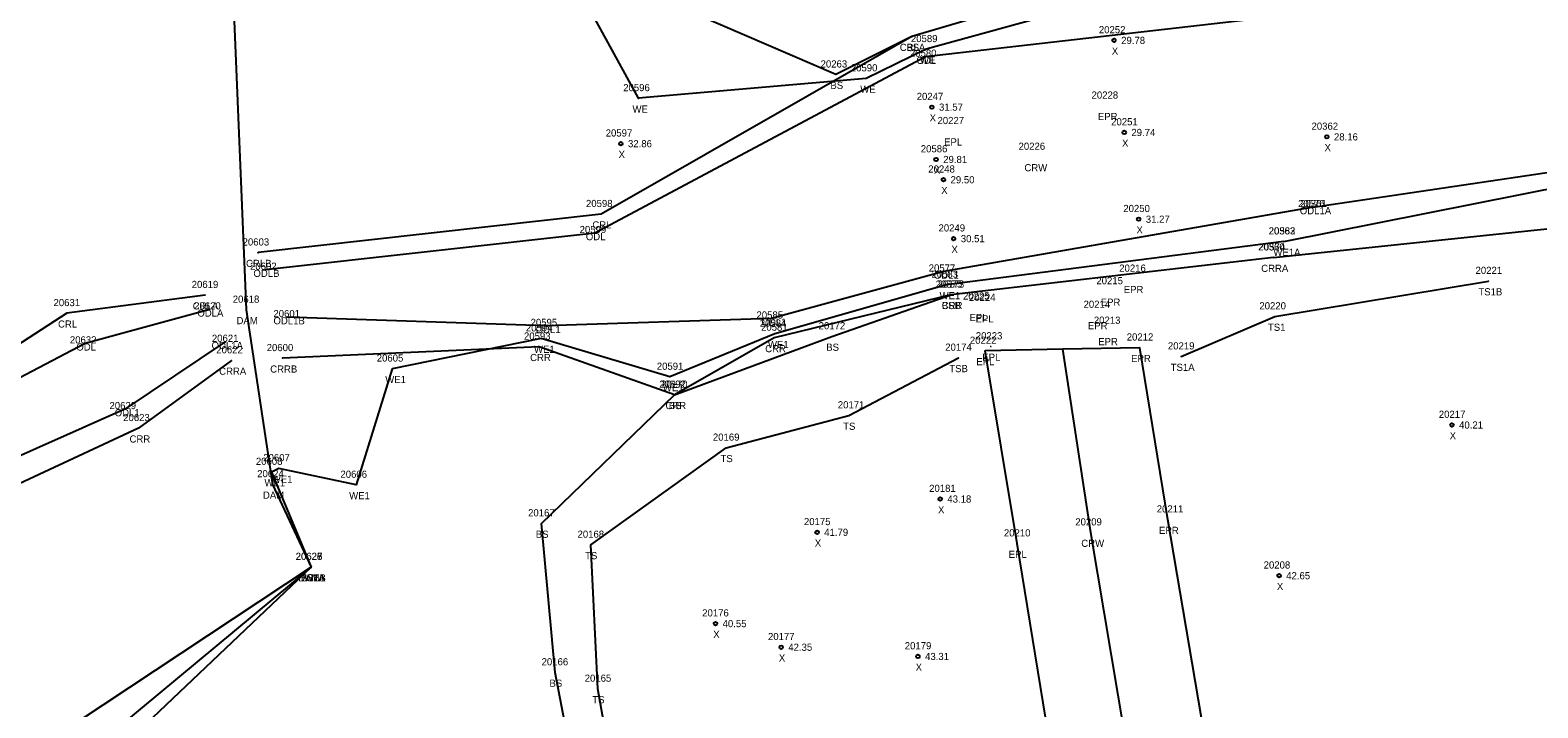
# Model space of a CAD drawing. Extents: x 2445178 to 2446260, y 791158 to 792318.
# Drawn here: x 2445572.9 to 2445783.8, y 791715.3 to 791810 of the extents above; entities that cross this region are included whole.
import ezdxf

# ---------------------------------------------------------------- set-up
doc = ezdxf.new("R2010")
doc.units = 0
for name, color, linetype in [('RD_DTM_BkLn1', 7, 'Continuous'), ('RD_DTM_BkLn2', 7, 'Continuous'), ('RD_EX_Dam', 7, 'Continuous'), ('RD_EX_Dam_txCode', 7, 'Continuous'), ('RD_EX_H2O', 7, 'Continuous'), ('RD_EX_H2O_txCode', 7, 'Continuous'), ('RD_EX_Road', 7, 'Continuous'), ('RD_EX_Road_txCode', 7, 'Continuous'), ('RD_Sketch8', 7, 'Continuous'), ('RD_SMD_Locator', 7, 'Continuous'), ('RD_SMD_Misc', 7, 'Continuous')]:
    doc.layers.add(name, color=color, linetype=linetype)

msp = doc.modelspace()

# ---------------------------------------------------------------- linework, layer by layer
at = {"layer": 'RD_DTM_BkLn1'}
for points in [[(2445728.16, 791765.65), (2445717.39, 791765.43), (2445706.49, 791765.2)], [(2445860.1, 791179.04), (2445833.11, 791268.21), (2445816.53, 791324.11), (2445799.46, 791383.44), (2445783.89, 791440.59), (2445769.57, 791497.35), (2445755.95, 791556.11), (2445741.36, 791625.36), (2445732.84, 791671.31), (2445721.28, 791739.8), (2445717.39, 791765.43)]]:
    msp.add_lwpolyline(points, dxfattribs=at)
at = {"layer": 'RD_DTM_BkLn2'}
for points in [[(2445721.97, 791816.74), (2445696.27, 791809.15), (2445685.63, 791803.83), (2445656.7, 791816.36), (2445642.32, 791839.59), (2445634.31, 791862.06), (2445625.81, 791909.02), (2445601.16, 791980.42), (2445587.75, 792035.69), (2445589.15, 792093.24), (2445629.12, 792201.55), (2445634.25, 792303.36)], [(2445733.92, 791764.41), (2445747.04, 791770.01), (2445776.96, 791774.97)], [(2445660.9, 791679.61), (2445652.02, 791690.62), (2445646.32, 791720.24), (2445644.41, 791741.07), (2445663.02, 791759.06), (2445685.05, 791767.22), (2445701.7, 791773.05)], [(2445660.9, 791679.61), (2445657.03, 791691.38), (2445652.33, 791717.94), (2445651.33, 791738.08), (2445670.27, 791751.65), (2445687.44, 791756.17), (2445702.76, 791764.23)], [(2445612.18, 791734.98), (2445557.56, 791698.84), (2445552.02, 791673.05), (2445513.68, 791664.7), (2445463.32, 791637.22), (2445363.77, 791592.3), (2445292.26, 791558.82)], [(2445612.18, 791734.98), (2445563.15, 791688.49), (2445558.95, 791665.85), (2445520.9, 791652.98), (2445473.7, 791621.85), (2445363.77, 791592.3)]]:
    msp.add_lwpolyline(points, dxfattribs=at)
at = {"layer": 'RD_EX_Dam'}
msp.add_lwpolyline([(2445642.32, 791839.59), (2445601.3, 791814.78), (2445603.08, 791770.94), (2445606.78, 791746.54), (2445612.18, 791734.98)], dxfattribs=at)
at = {"layer": 'RD_EX_H2O'}
for points in [[(2445748.32, 791780.49), (2445788.24, 791788.44), (2445846, 791811.01), (2445891.85, 791826.96), (2445872.2, 791885.31), (2445911.58, 791917.24), (2445942.41, 791930.41), (2445989.95, 791963.2), (2446004.43, 791957.67), (2446037.13, 791928.19), (2446062.94, 791924.63), (2446122.42, 791925.89), (2446133.98, 791956.62), (2446163.05, 791958.48), (2446202.11, 792005.16)], [(2445752.43, 791785.31), (2445788.27, 791790.61), (2445845.46, 791813.31), (2445889.72, 791828.98), (2445868.44, 791886.37), (2445910.27, 791920.69), (2445939.62, 791931.64), (2445988.31, 791964.33), (2446005.31, 791961.03), (2446034.89, 791932.66), (2446061.86, 791927.42), (2446120.16, 791928.99), (2446131.56, 791958.98), (2446161.23, 791962.03), (2446198.32, 792006.02)], [(2445746.88, 791778.25), (2445790.91, 791782.86), (2445846.87, 791809.11), (2445896.01, 791824.25), (2445877, 791883.78), (2445912.26, 791916.16), (2445942.78, 791927.77), (2445991.6, 791962.06), (2446003.69, 791956.06), (2446036.32, 791927.07), (2446060.96, 791923.67), (2446122.97, 791923.97), (2446134.24, 791956.18), (2446163.21, 791958.01), (2446202.51, 792004.24)], [(2445757.3, 791817.48), (2445724.23, 791814.58), (2445698.23, 791807.38), (2445689.87, 791803.29), (2445658, 791800.52), (2445641.81, 791830.07), (2445642.32, 791839.59), (2445634.31, 791862.06), (2445625.81, 791909.02), (2445601.16, 791980.42)], [(2445756.08, 791812.92), (2445698.14, 791806.34), (2445651.88, 791781.68), (2445605.82, 791776.55)], [(2445696.27, 791809.15), (2445652.77, 791784.32), (2445604.79, 791778.94)], [(2445752.43, 791785.31), (2445700.73, 791776.3), (2445676.63, 791769.73), (2445645.02, 791768.69), (2445608.81, 791769.92)], [(2445748.32, 791780.49), (2445701.12, 791774.43), (2445677.09, 791767.59), (2445662.39, 791761.56), (2445644.36, 791766.93), (2445623.55, 791762.71), (2445618.49, 791746.46), (2445607.67, 791748.78), (2445606.64, 791748.27), (2445612.18, 791734.98), (2445561.56, 791692.97), (2445554.1, 791670.89), (2445517.8, 791656.91), (2445473.7, 791621.85), (2445363.77, 791592.3), (2445292.26, 791558.82)], [(2445746.88, 791778.25), (2445701.7, 791773.05), (2445676.99, 791767.02), (2445663.02, 791759.06), (2445644.08, 791765.78), (2445608.19, 791764.17)], [(2445597.34, 791773), (2445578, 791770.46), (2445544.99, 791749.08)], [(2445598, 791771), (2445580.58, 791766.25), (2445545.35, 791747.76), (2445529.9, 791743.48), (2445493.64, 791702.86), (2445469.99, 791696.32), (2445420.2, 791747.49), (2445408.65, 791738.85), (2445398.22, 791720.47), (2445370.93, 791678.47), (2445333.32, 791699.47), (2445304.17, 791689.05), (2445297.68, 791600.13), (2445290.12, 791566.49)], [(2445600.16, 791766.47), (2445586.11, 791757.06), (2445543.42, 791738.09), (2445500.69, 791690.42), (2445463.87, 791687.89), (2445423.05, 791739.22), (2445412.07, 791732.11), (2445402.24, 791718.7), (2445377.05, 791678.37), (2445370.6, 791674.92), (2445335.15, 791693.03), (2445306.01, 791687.27), (2445304.48, 791597.26), (2445303.65, 791580.6), (2445291.47, 791560.13)], [(2445601.06, 791763.87), (2445588.04, 791754.39), (2445544.11, 791733.92), (2445501.1, 791687.67), (2445464.95, 791685.09), (2445422.11, 791733.61), (2445413.32, 791729.6), (2445404.23, 791718.68), (2445377.21, 791675.18), (2445369.95, 791673.71), (2445335.95, 791691.26), (2445308.99, 791685.23), (2445308.22, 791596.59), (2445306.48, 791581.14), (2445293.31, 791557.11)]]:
    msp.add_lwpolyline(points, dxfattribs=at)
at = {"layer": 'RD_EX_Road'}
for points in [[(2445850.42, 791174.36), (2445823.13, 791264.7), (2445806.34, 791321.46), (2445789.41, 791379.89), (2445773.46, 791437.57), (2445759.36, 791494.22), (2445744.01, 791559.83), (2445740.09, 791577.64), (2445731.05, 791621.01), (2445722.21, 791669.43), (2445711, 791738.26), (2445706.49, 791765.2)], [(2445870.82, 791182.02), (2445844.02, 791271.27), (2445827.31, 791326.39), (2445810.32, 791385.52), (2445794.94, 791441.92), (2445780.98, 791497.5), (2445766.72, 791558.1), (2445751.9, 791628.3), (2445743.63, 791673.52), (2445732.07, 791741.61), (2445728.16, 791765.65)]]:
    msp.add_lwpolyline(points, dxfattribs=at)
at = {"layer": 'RD_SMD_Locator'}
for centre, radius in [((2445696.27, 791809.15), 0.001), ((2445696.27, 791809.15), 0.001), ((2445724.54, 791808.62), 0.25), ((2445698.23, 791807.38), 0.001), ((2445698.14, 791806.34), 0.001), ((2445685.63, 791803.83), 0.001), ((2445689.87, 791803.29), 0.001), ((2445658, 791800.52), 0.001), ((2445699.05, 791799.29), 0.25), ((2445725.97, 791795.75), 0.25), ((2445655.53, 791794.18), 0.25), ((2445754.32, 791795.13), 0.25), ((2445699.64, 791791.97), 0.25), ((2445700.67, 791789.14), 0.25), ((2445652.77, 791784.32), 0.001), ((2445727.99, 791783.62), 0.25), ((2445752.43, 791785.31), 0.001), ((2445752.43, 791785.31), 0.001), ((2445651.88, 791781.68), 0.001), ((2445702.1, 791780.9), 0.25), ((2445748.32, 791780.49), 0.001), ((2445748.32, 791780.49), 0.001), ((2445604.79, 791778.94), 0.001), ((2445746.88, 791778.25), 0.001), ((2445746.88, 791778.25), 0.001), ((2445605.82, 791776.55), 0.001), ((2445700.73, 791776.3), 0.001), ((2445776.96, 791774.97), 0.001), ((2445597.34, 791773), 0.001), ((2445701.12, 791774.43), 0.001), ((2445701.7, 791773.05), 0.001), ((2445701.7, 791773.05), 0.001), ((2445598, 791771), 0.001), ((2445603.08, 791770.94), 0.001), ((2445578, 791770.46), 0.001), ((2445608.81, 791769.92), 0.001), ((2445645.02, 791768.69), 0.001), ((2445676.63, 791769.73), 0.001), ((2445747.04, 791770.01), 0.001), ((2445600.16, 791766.47), 0.001), ((2445644.36, 791766.93), 0.001), ((2445676.99, 791767.02), 0.001), ((2445677.09, 791767.59), 0.001), ((2445685.05, 791767.22), 0.001), ((2445580.58, 791766.25), 0.001), ((2445644.08, 791765.78), 0.001), ((2445706.49, 791765.2), 0.001), ((2445707.32, 791765.82), 0.001), ((2445728.16, 791765.65), 0.001), ((2445733.92, 791764.41), 0.001), ((2445601.06, 791763.87), 0.001), ((2445608.19, 791764.17), 0.001), ((2445623.55, 791762.71), 0.001), ((2445702.76, 791764.23), 0.001), ((2445662.39, 791761.56), 0.001), ((2445663.02, 791759.06), 0.001), ((2445663.02, 791759.06), 0.001), ((2445586.11, 791757.06), 0.001), ((2445687.44, 791756.17), 0.001), ((2445588.04, 791754.39), 0.001), ((2445771.83, 791754.84), 0.25), ((2445670.27, 791751.65), 0.001), ((2445606.64, 791748.27), 0.001), ((2445607.67, 791748.78), 0.001), ((2445606.78, 791746.54), 0.001), ((2445618.49, 791746.46), 0.001), ((2445700.22, 791744.49), 0.25), ((2445732.07, 791741.61), 0.001), ((2445644.41, 791741.07), 0.001), ((2445682.99, 791739.84), 0.25), ((2445721.28, 791739.8), 0.001), ((2445651.33, 791738.08), 0.001), ((2445711, 791738.26), 0.001), ((2445612.18, 791734.98), 0.001), ((2445612.18, 791734.98), 0.001), ((2445612.18, 791734.98), 0.001), ((2445612.18, 791734.98), 0.001), ((2445747.64, 791733.77), 0.25), ((2445668.77, 791727.07), 0.25), ((2445677.96, 791723.77), 0.25), ((2445697.1, 791722.48), 0.25), ((2445646.32, 791720.24), 0.001), ((2445652.33, 791717.94), 0.001)]:
    msp.add_circle(centre, radius, dxfattribs=at)

# ---------------------------------------------------------------- texts
at = {"layer": 'RD_EX_Dam_txCode'}
for s, p in [('20618', (2445601.22, 791771.94)), ('DAM', (2445601.75, 791768.94)), ('20624', (2445604.64, 791747.54)), ('DAM', (2445605.45, 791744.54)), ('20625', (2445610.04, 791735.98)), ('DAMB', (2445610.38, 791732.98))]:
    msp.add_text(s, height=1, dxfattribs=at).set_placement(p)
at = {"layer": 'RD_EX_H2O_txCode'}
for s, p in [('20589', (2445696.12, 791808.38)), ('CRLA', (2445694.56, 791807.15)), ('20580', (2445695.98, 791806.34)), ('20590', (2445687.71, 791804.29)), ('ODL', (2445696.9, 791805.34)), ('WE', (2445697.39, 791805.38)), ('20596', (2445655.86, 791801.52)), ('WE', (2445689.03, 791801.29)), ('WE', (2445657.16, 791798.52)), ('20598', (2445650.65, 791785.32)), ('20576', (2445750.29, 791785.31)), ('20361', (2445750.58, 791785.31)), ('CRL', (2445651.54, 791782.32)), ('ODL1A', (2445750.54, 791784.31)), ('ODL1A', (2445750.54, 791784.31)), ('20599', (2445649.76, 791781.68)), ('ODL', (2445650.63, 791780.68)), ('20363', (2445746.17, 791781.49)), ('20582', (2445746.2, 791781.49)), ('20603', (2445602.6, 791779.94)), ('20360', (2445744.7, 791779.25)), ('20574', (2445744.76, 791779.25)), ('WE1A', (2445746.84, 791778.49)), ('WE1A', (2445746.84, 791778.49)), ('CRLB', (2445603.08, 791776.94)), ('20602', (2445603.64, 791776.55)), ('20577', (2445698.61, 791776.3)), ('CRRA', (2445745.14, 791776.25)), ('CRRA', (2445745.14, 791776.25)), ('20619', (2445595.48, 791774)), ('ODLB', (2445604.11, 791775.55)), ('20583', (2445699, 791775.43)), ('ODL1', (2445699.32, 791775.3)), ('20575', (2445699.58, 791774.05)), ('WE1', (2445700.13, 791772.43)), ('20631', (2445576.14, 791771.46)), ('CRLA', (2445595.62, 791771)), ('20620', (2445595.82, 791771)), ('ODLA', (2445596.27, 791770)), ('20601', (2445606.91, 791769.92)), ('20585', (2445674.51, 791769.73)), ('CRR', (2445700.44, 791771.05)), ('CRL', (2445576.77, 791768.46)), ('ODL1B', (2445606.92, 791768.92)), ('20594', (2445642.24, 791767.93)), ('20595', (2445642.9, 791768.69)), ('ODL1', (2445643.61, 791767.69)), ('20584', (2445674.97, 791768.59)), ('20581', (2445675.15, 791768.02)), ('ODL1', (2445675.22, 791768.73)), ('20632', (2445578.43, 791766.25)), ('ODL1A', (2445598.26, 791765.47)), ('20621', (2445598.3, 791766.47)), ('20593', (2445641.97, 791766.78)), ('WE1', (2445676.11, 791765.59)), ('ODL', (2445579.33, 791765.25)), ('20622', (2445598.92, 791764.87)), ('20600', (2445605.97, 791765.17)), ('20605', (2445621.37, 791763.71)), ('CRR', (2445642.83, 791763.78)), ('WE1', (2445643.38, 791764.93)), ('CRR', (2445675.73, 791765.02)), ('CRRA', (2445599.32, 791761.87)), ('CRRB', (2445606.46, 791762.17)), ('20591', (2445660.56, 791762.56)), ('WE1', (2445622.56, 791760.71)), ('20592', (2445660.9, 791760.06)), ('WE1', (2445661.41, 791759.56)), ('20629', (2445583.97, 791757.06)), ('CRR', (2445661.77, 791757.06)), ('ODL1', (2445584.7, 791756.06)), ('20623', (2445585.89, 791755.39)), ('CRR', (2445586.78, 791752.39)), ('20608', (2445604.46, 791749.27)), ('20607', (2445605.49, 791749.78)), ('WE1', (2445606.68, 791746.78)), ('20606', (2445616.29, 791747.46)), ('WE1', (2445605.66, 791746.27)), ('WE1', (2445617.51, 791744.46)), ('20626', (2445610.02, 791735.98)), ('WE1', (2445611.2, 791732.98))]:
    msp.add_text(s, height=1, dxfattribs=at).set_placement(p)
at = {"layer": 'RD_EX_Road_txCode'}
for s, p in [('20228', (2445721.4, 791800.48)), ('EPR', (2445722.28, 791797.48)), ('20227', (2445699.84, 791796.92)), ('EPL', (2445700.76, 791793.92)), ('20216', (2445725.27, 791776.28)), ('20215', (2445722.07, 791774.52)), ('20225', (2445703.41, 791772.38)), ('20224', (2445704.24, 791772.19)), ('EPR', (2445725.9, 791773.28)), ('20214', (2445720.28, 791771.23)), ('EPR', (2445722.68, 791771.52)), ('EPL', (2445704.32, 791769.38)), ('EPL', (2445705.16, 791769.19)), ('EPR', (2445720.88, 791768.23)), ('20213', (2445721.72, 791769)), ('20222', (2445704.37, 791766.2)), ('20223', (2445705.2, 791766.82)), ('EPR', (2445722.33, 791766)), ('20212', (2445726.32, 791766.65)), ('EPL', (2445706.11, 791763.82)), ('EPR', (2445726.93, 791763.65)), ('EPL', (2445705.28, 791763.2)), ('20211', (2445730.52, 791742.61)), ('20210', (2445709.13, 791739.26)), ('EPR', (2445730.84, 791739.61)), ('EPL', (2445709.8, 791736.26))]:
    msp.add_text(s, height=1, dxfattribs=at).set_placement(p)
at = {"layer": 'RD_Sketch8'}
for s, p in [('20252', (2445722.42, 791809.62)), ('29.78', (2445725.54, 791808.12)), ('X', (2445724.23, 791806.62)), ('20247', (2445696.93, 791800.29)), ('X', (2445698.74, 791797.29)), ('31.57', (2445700.05, 791798.79)), ('20597', (2445653.41, 791795.18)), ('20251', (2445724.14, 791796.75)), ('29.74', (2445726.97, 791795.25)), ('20362', (2445752.18, 791796.13)), ('32.86', (2445656.53, 791793.68)), ('20586', (2445697.5, 791792.97)), ('X', (2445725.66, 791793.75)), ('X', (2445754, 791793.13)), ('28.16', (2445755.32, 791794.63)), ('X', (2445655.21, 791792.18)), ('29.81', (2445700.64, 791791.47)), ('20248', (2445698.55, 791790.14)), ('X', (2445699.33, 791789.97)), ('29.50', (2445701.67, 791788.64)), ('X', (2445700.36, 791787.14)), ('20250', (2445725.84, 791784.62)), ('31.27', (2445728.99, 791783.12)), ('20249', (2445699.98, 791781.9)), ('30.51', (2445703.1, 791780.4)), ('X', (2445727.68, 791781.62)), ('X', (2445701.79, 791778.9)), ('20217', (2445769.99, 791755.84)), ('X', (2445771.51, 791752.84)), ('40.21', (2445772.83, 791754.34)), ('20181', (2445698.67, 791745.49)), ('X', (2445699.91, 791742.49)), ('43.18', (2445701.22, 791743.99)), ('20175', (2445681.15, 791740.84)), ('41.79', (2445683.99, 791739.34)), ('X', (2445682.67, 791737.84)), ('20208', (2445745.48, 791734.77)), ('X', (2445747.33, 791731.77)), ('42.65', (2445748.64, 791733.27)), ('20176', (2445666.91, 791728.07)), ('40.55', (2445669.77, 791726.57)), ('X', (2445668.46, 791725.07)), ('20177', (2445676.12, 791724.77)), ('42.35', (2445678.96, 791723.27)), ('20179', (2445695.26, 791723.48)), ('X', (2445677.64, 791721.77)), ('43.31', (2445698.1, 791721.98)), ('X', (2445696.78, 791720.48))]:
    msp.add_text(s, height=1, dxfattribs=at).set_placement(p)
at = {"layer": 'RD_SMD_Misc'}
for s, p in [('BS', (2445695.49, 791807.15)), ('20263', (2445683.48, 791804.83)), ('BS', (2445684.85, 791801.83)), ('20226', (2445711.18, 791793.32)), ('CRW', (2445712, 791790.32)), ('20221', (2445775.13, 791775.97)), ('20173', (2445699.86, 791774.05)), ('TS1B', (2445775.53, 791772.97)), ('BSB', (2445700.44, 791771.05)), ('20220', (2445744.88, 791771.01)), ('20172', (2445683.21, 791768.22)), ('TS1', (2445746.08, 791768.01)), ('20219', (2445732.08, 791765.41)), ('BS', (2445684.27, 791765.22)), ('20174', (2445700.92, 791765.23)), ('TSB', (2445701.49, 791762.23)), ('TS1A', (2445732.47, 791762.41)), ('20170', (2445661.14, 791760.06)), ('BS', (2445662.24, 791757.06)), ('20171', (2445685.89, 791757.17)), ('TS', (2445686.64, 791754.17)), ('20169', (2445668.41, 791752.65)), ('TS', (2445669.47, 791749.65)), ('20167', (2445642.55, 791742.07)), ('20209', (2445719.12, 791740.8)), ('BS', (2445643.63, 791739.07)), ('20168', (2445649.47, 791739.08)), ('20627', (2445610.04, 791735.98)), ('20628', (2445610.04, 791735.98)), ('TS', (2445650.53, 791736.08)), ('CRW', (2445719.96, 791737.8)), ('TS1A', (2445610.74, 791732.98)), ('BS1A', (2445610.75, 791732.98)), ('20166', (2445644.44, 791721.24)), ('BS', (2445645.54, 791718.24)), ('20165', (2445650.47, 791718.94)), ('TS', (2445651.54, 791715.94))]:
    msp.add_text(s, height=1, dxfattribs=at).set_placement(p)

doc.saveas('drawing.dxf')
